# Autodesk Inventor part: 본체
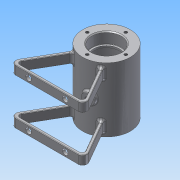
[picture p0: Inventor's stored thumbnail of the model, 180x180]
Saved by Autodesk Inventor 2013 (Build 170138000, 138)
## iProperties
Created: 2016-03
Part Number: 본체
Material: 알루미늄 6061
Document SubType Name: Modeling
Designer: Administrator
Density: 2.71 g/cm^3
Mass: 213.518 g
Surface Area: 333.684 cm^2
Volume: 78.7891 cm^3
Author: Administrator
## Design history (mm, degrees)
sketch "스케치1"
  geometry: C1 r 26 at (0, 0); 1 further point
  constraints: 1 centre point, 1 coincident
  dimensions: "d0" = 52 diameter of C1
extrude "돌출1" new body sketch "스케치1" stored distance "d1" = 70; taper "d2" = 0 deg
node "작업 평면1"
sketch "스케치2"
  geometry: L1 (0, 0)-(0, -65); L2 (-42.594, -65)-(42.594, -65); L3 (42.594, -65)-(0, 8.775); L4 (-42.594, -65)-(0, 8.775); C1 r 26 at (0, 0) reference
  constraints: 8 end point, 1 midpoint, 1 perpendicular, 1 vertical, 1 other
  dimensions: "d4" = 65 distance of L1.end L1.start; "d5" = 60 deg angle of L2 L3; "d7" = 85.18802 distance of L2.start L2.end
feature "리브1" sketch "스케치2" dims "d8" = 3, "d9" = 10, "d10" = 0, "d11" = 0, "d12" = 1, "d13" = 1
node "작업 평면2"
sketch "스케치3"
  geometry: C1 r 5 at (0, 0); 1 further point
  constraints: 1 centre point, 1 coincident
  dimensions: "d15" = 10 diameter of C1
extrude "돌출2" join sketch "스케치3" stored distance "d16" = 70; taper "d17" = 0 deg
sketch "스케치4"
  geometry: L1 (0, 0)-(7.506, -28.012); L2 (0, 0)-(0, -28.03); C1 r 26 at (0, 0) reference; 1 further point
  constraints: 4 end point, 1 vertical
  dimensions: "d18" = 29 distance of L1.start L1.end; "d19" = 15 deg angle of L1 L2
  node "투영된 루프2"
node "작업 평면3"
sketch "스케치5"
  geometry: C1 r 6 at (0, 0); 1 further point
  constraints: 1 centre point, 1 coincident
  dimensions: "d20" = 12 diameter of C1
extrude "돌출3" join sketch "스케치5" stored distance "d21" = 70; taper "d22" = 0 deg
sketch "스케치6"
  geometry: C1 r 26 at (0, 0) reference; C2 r 16 at (0, 0)
  constraints: 1 centre point, 1 coincident
  dimensions: "d23" = 32 diameter of C2
extrude "돌출4" cut sketch "스케치6" distance "d24" = 12; taper "d25" = 0 deg
sketch "스케치7"
  geometry: C1 r 26 at (0, 0) reference; C2 r 16 at (0, 0)
  constraints: 1 centre point, 1 coincident
  dimensions: "d26" = 32 diameter of C2
extrude "돌출5" cut sketch "스케치7" distance "d27" = 12; taper "d28" = 0 deg
sketch "스케치8"
  geometry: C1 r 21 at (0, 0); 1 further point
  constraints: 1 centre point, 1 coincident
  dimensions: "d29" = 42 diameter of C1
extrude "돌출6" cut sketch "스케치8" stored distance "d30" = 42; taper "d31" = 0 deg
sketch "스케치9"
  geometry: C1 r 16 at (0, 0) reference; C2 r 14 at (0, 0)
  constraints: 1 centre point, 1 coincident
  dimensions: "d32" = 28 diameter of C2
extrude "돌출7" cut sketch "스케치9" stored distance "d33" = 42; taper "d34" = 0 deg
sketch "스케치10"
  geometry: C1 r 16 at (0, 0) reference; 1 further point
  constraints: 1 vertical alignment
  dimensions: "d35" = 21 distance of C1.centre point (0, 21)
hole "구멍1" sketch "스케치10" at (0, 21) diameter "d36" = 3.242; stored, may be unused: countersink angle "d40" = 90 deg, drill point angle "d42" = 118 deg; dims "d37" = 8, "d38" = 4, "d39" = 2, "d41" = 10
hole "구멍2" diameter "d48" = 5.188; stored, may be unused: countersink angle "d52" = 90 deg, drill point angle "d54" = 118 deg; dims "d46" = 10, "d47" = 10, "d49" = 30, "d50" = 4, "d51" = 2, "d53" = 10
hole "구멍3" diameter "d57" = 5.188; stored, may be unused: countersink angle "d61" = 90 deg, drill point angle "d63" = 118 deg; dims "d58" = 20, "d59" = 4, "d60" = 2, "d62" = 10, "d64" = 10, "d65" = 10
fillet "모깎기1" dims "d66" = 2
fillet "모깎기2" dims "d67" = 5
fillet "모깎기3" dims "d68" = 3
fillet "모깎기4" dims "d69" = 0.5
fillet "모깎기5" dims "d70" = 3
fillet "모깎기6" dims "d71" = 0.3
fillet "모깎기7" dims "d72" = 3
chamfer "모따기1" distance "d73" = 1; stored, may be unused: second distance "d74" = 2, angle "d75" = 45 deg
sketch "스케치11"
  geometry: L1 (-6.232, 0.5)-(-1.732, 0.5) reference; C1 r 3 at (12.202, -4.5); C2 r 3 at (52.202, -4.5); 2 further points
  constraints: 2 centre point, 1 horizontal alignment
  dimensions: "d76" = 6 diameter of C1; "d77" = 6 diameter of C2; "d78" = 20 horizontal distance of point (32.202, -29.5) C1.centre; "d79" = 5 distance from line of C1.centre L1; "d80" = 40 distance of C2.centre C1.centre
extrude "돌출8" cut sketch "스케치11" stored distance "d81" = 42; taper "d82" = 0 deg
node "작업 평면4"
sketch "스케치12"
  geometry: 2 further points
  constraints: 1 coincident, 1 other
feature "엠보싱1" sketch "스케치12" dims "d83" = 0.5, "d84" = 0
node "솔리드1"
mirror "대칭1"
pattern_circular "원형 패턴1" dims angle "d44" = 360 deg
mirror "대칭2"
mirror "대칭3"
node "투영된 루프1"
other parameters: "d14" = 29
